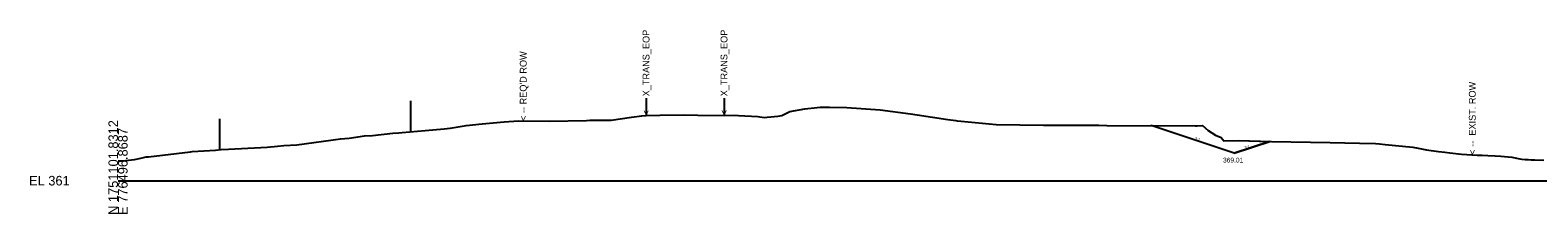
# Model space of a CAD drawing. Extents: x 776426 to 854588, y 1736205 to 1756790.
# Drawn here: x 805845.1 to 806285.9, y 1736705.1 to 1736758.7 of the extents above; entities that cross this region are included whole.
import ezdxf

# ---------------------------------------------------------------- set-up
doc = ezdxf.new("R2010")
doc.units = 0
for name, color, linetype in [('DTM CONTOURS_MAJOR_TX', 7, 'Continuous'), ('DTM_X_FLOW_ARROWS', 7, 'Continuous'), ('TRANS_UNPAVED_SHOULDERS', 7, 'Continuous'), ('X_TRANS_EOP', 7, 'Continuous'), ('XS_M_SHAPES_EARTHWORK', 7, 'Continuous'), ('XS_P_FINISHED_GRADE', 7, 'Continuous'), ('XS_P_ROW', 7, 'Continuous'), ('XS_P_TX_DCH', 7, 'Continuous'), ('XS_P_TX_FS_BS', 7, 'Continuous'), ('XS_X_PAVEMENT', 7, 'Continuous'), ('XS_X_ROW', 7, 'Continuous')]:
    doc.layers.add(name, color=color, linetype=linetype)

msp = doc.modelspace()

# ---------------------------------------------------------------- linework, layer by layer
at = {"layer": 'DTM CONTOURS_MAJOR_TX'}
msp.add_line((805870.79, 1736714.76), (806370.79, 1736714.76), dxfattribs=at)
at = {"layer": 'DTM_X_FLOW_ARROWS'}
msp.add_lwpolyline([(805870.79, 1736720.52), (805872.14, 1736720.6), (805873.82, 1736720.75), (805875.56, 1736720.94), (805877.43, 1736721.35), (805879.05, 1736721.73), (805879.66, 1736721.72), (805891.96, 1736723.23), (805892.45, 1736723.29), (805899.31, 1736723.72), (805900.91, 1736723.83), (805903.07, 1736723.98), (805912.52, 1736724.42), (805914.39, 1736724.57), (805917.38, 1736724.89), (805919.27, 1736725), (805923.08, 1736725.27), (805935.86, 1736726.94), (805938.36, 1736727.23), (805942.88, 1736727.9), (805945.18, 1736728.01), (805951.13, 1736728.62), (805952.85, 1736728.77), (805953.83, 1736728.87), (805960.57, 1736729.42), (805966.13, 1736729.87), (805967.84, 1736730.15), (805972.58, 1736730.89), (805977.25, 1736731.41), (805983.63, 1736731.92), (805987.88, 1736732.22), (805996.94, 1736732.2), (806007.74, 1736732.39), (806008.69, 1736732.43), (806014.95, 1736732.48), (806020.87, 1736733.3), (806023.96, 1736733.74), (806025.16, 1736733.83), (806029.14, 1736733.9), (806036.41, 1736733.99), (806040.31, 1736733.92), (806047.94, 1736733.85), (806051.08, 1736733.86), (806052.13, 1736733.82), (806057.85, 1736733.52), (806059.68, 1736733.27), (806060.52, 1736733.28), (806063.69, 1736733.66), (806064.81, 1736733.79), (806067.15, 1736734.98), (806071.55, 1736735.76), (806075.2, 1736736.19), (806076.02, 1736736.21), (806078.78, 1736736.28), (806083.87, 1736736.12), (806093.58, 1736735.45), (806102.42, 1736734.29), (806104.37, 1736734.02), (806113.37, 1736732.65), (806115.67, 1736732.31), (806116.08, 1736732.24), (806117.23, 1736732.11), (806127.51, 1736731.17), (806141.31, 1736731.02), (806141.63, 1736731.02), (806153.17, 1736731.01), (806153.83, 1736731), (806157.49, 1736730.94), (806159.88, 1736730.92), (806185.75, 1736730.8), (806186.26, 1736730.83), (806187.78, 1736730.88), (806189.49, 1736729.38), (806191.6, 1736728.07), (806193.23, 1736727.34), (806194.01, 1736726.44), (806198.36, 1736726.5), (806207.95, 1736726.23), (806219.42, 1736726.04), (806225.1, 1736725.89), (806233.73, 1736725.7), (806238.37, 1736725.62), (806239.57, 1736725.48), (806241.27, 1736725.32), (806249.28, 1736724.55), (806250.83, 1736724.27), (806252.86, 1736723.86), (806253.29, 1736723.82), (806256.86, 1736723.27), (806258.62, 1736723.11), (806260.13, 1736722.89), (806263.51, 1736722.53), (806268.08, 1736722.26), (806269.62, 1736722.19), (806271.25, 1736722.11), (806273.41, 1736722.04), (806275.05, 1736721.91), (806278.28, 1736721.64), (806280.62, 1736721.14), (806281.16, 1736721.03), (806282.17, 1736720.96), (806283.05, 1736720.91), (806283.94, 1736720.82), (806284.93, 1736720.81), (806287.56, 1736720.72)], dxfattribs=at)
at = {"layer": 'TRANS_UNPAVED_SHOULDERS'}
for p, q in [((805956.25, 1736738.07), (805956.25, 1736729.07)), ((805956.25, 1736738.07), (805956.25, 1736729.07)), ((805900.41, 1736732.8), (805900.41, 1736723.8)), ((805900.41, 1736732.8), (805900.41, 1736723.8))]:
    msp.add_line(p, q, dxfattribs=at)
at = {"layer": 'X_TRANS_EOP'}
for p, q in [((806025.15, 1736738.83), (806025.15, 1736733.83)), ((806025.15, 1736738.83), (806025.15, 1736733.83)), ((806047.94, 1736738.85), (806047.94, 1736733.85)), ((806047.94, 1736738.85), (806047.94, 1736733.85))]:
    msp.add_line(p, q, dxfattribs=at)
at = {"layer": 'XS_M_SHAPES_EARTHWORK'}
msp.add_lwpolyline([(806189.49, 1736729.38), (806191.6, 1736728.07), (806193.23, 1736727.34), (806194.01, 1736726.44), (806198.36, 1736726.5), (806207.48, 1736726.24), (806197.08, 1736722.77), (806172.81, 1736730.86), (806185.75, 1736730.8), (806186.26, 1736730.83), (806187.78, 1736730.88)], close=True, dxfattribs=at)
at = {"layer": 'XS_P_FINISHED_GRADE'}
for q in [(806172.81, 1736730.86), (806207.48, 1736726.24)]:
    msp.add_line((806197.08, 1736722.77), q, dxfattribs=at)

# ---------------------------------------------------------------- texts
at = {"layer": 'DTM CONTOURS_MAJOR_TX'}
for s, p in [('N 1751101.8312', (805870.79, 1736704.76)), ('E 776496.8687', (805873.59, 1736704.76))]:
    msp.add_text(s, height=2.8, rotation=90, dxfattribs=at).set_placement(p)
msp.add_text('EL 361', height=2.8, dxfattribs=at).set_placement((805844.79, 1736713.36))
at = {"layer": 'XS_P_ROW'}
msp.add_text("< -- REQ'D ROW", height=2, rotation=90, dxfattribs=at).set_placement((805990.24, 1736732.22))
at = {"layer": 'XS_P_TX_DCH'}
msp.add_text('369.01', height=1.4, dxfattribs=at).set_placement((806193.82, 1736720.07))
at = {"layer": 'XS_P_TX_FS_BS'}
for rotation, p in [(341.5651, (806185.5, 1736726.83)), (18.4349, (806200.28, 1736723.99))]:
    msp.add_text('3:1', height=0.8, rotation=rotation, dxfattribs=at).set_placement(p)
at = {"layer": 'XS_X_PAVEMENT'}
for p in [(806026.15, 1736733.83), (806048.94, 1736733.85)]:
    msp.add_text('< --  X_TRANS_EOP', height=2, rotation=90, dxfattribs=at).set_placement(p)
at = {"layer": 'XS_X_ROW'}
msp.add_text('< --  EXIST. ROW', height=2, rotation=90, dxfattribs=at).set_placement((806267.69, 1736722.34))

doc.saveas('drawing.dxf')
